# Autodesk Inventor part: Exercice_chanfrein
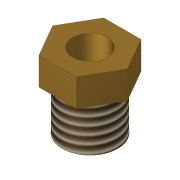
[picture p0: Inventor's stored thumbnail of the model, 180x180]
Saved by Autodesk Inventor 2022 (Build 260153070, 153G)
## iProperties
Created: 2018-06
Part Number: Exercice_chanfrein
Material: Laiton, jaune doux
Document SubType Name: Modeling
Designer: Fabian Perrée
Density: 8.47 g/cm^3
Appearance: Laiton - Satiné
Author: Fabian Perrée
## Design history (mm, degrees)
sketch "Esquisse1"
  geometry: C1 r 6 at (0, 0); C2 r 3.75 at (0, 0); 1 further point
  constraints: 2 centre point, 2 coincident
  dimensions: "d0" = 12 diameter of C1; "d1" = 7.5 diameter of C2
extrude "Extrusion1" new body sketch "Esquisse1" distance "d2" = 16; taper "d3" = 0 deg
sketch "Esquisse2"
  geometry: L1 (4.041, -7)-(-4.041, -7); L2 (-4.041, -7)-(-8.083, 0); L3 (-8.083, 0)-(-4.041, 7); L4 (-4.041, 7)-(4.041, 7); L5 (4.041, 7)-(8.083, 0); L6 (8.083, 0)-(4.041, -7); C1 r 3.75 at (0, 0) reference; C2 r 6 at (0, 0) reference; 1 further point
  constraints: 12 end point, 1 coincident, 1 horizontal, 13 other
  dimensions: "d4" = 14 distance between parallel lines of L4 L1
extrude "Extrusion2" join sketch "Esquisse2" distance "d5" = 6; taper "d6" = 0 deg
feature "Filetage1" dims "d10" = 10, "d11" = 0
node "Solide1"
